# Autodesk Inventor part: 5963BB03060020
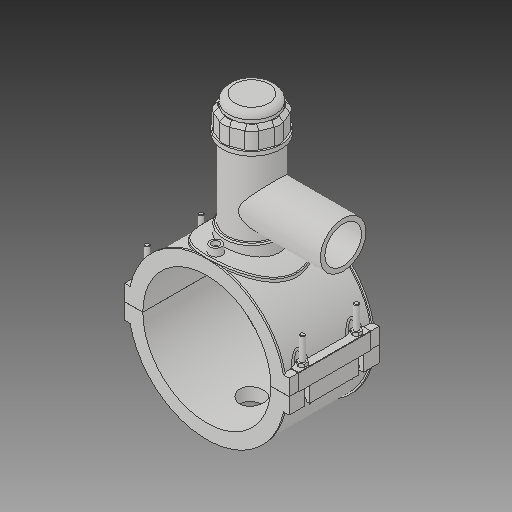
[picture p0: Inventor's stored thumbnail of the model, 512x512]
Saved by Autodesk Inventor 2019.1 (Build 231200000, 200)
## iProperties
Created: 2017-07
Part Number: 5963BB03060020
Material: Generic
Description: PLASSON TAPPING SADDLE 6''IPS x 2''IPS
Document SubType Name: Modeling
Designer: KIM
Mass: 1712.7 g
Surface Area: 2671.49 cm^2
Volume: 1712.7 cm^3
Density: 1 g/cm^3
Appearance: Default
Author: KIM
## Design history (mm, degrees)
derived "5963B.ipt"
feature "Solid1::5963B.ipt"
feature "Solid2::5963B.ipt"
feature "Solid4::5963B.ipt"
feature "Solid5::5963B.ipt"
tag "TaggingFeature1"
body "Solid1"
body "Solid2"
other parameters: "d0" = 168, "d2" = 215.9, "d3" = 42, "d4" = 118.11, "d5" = 0, "d6" = 0.1, "d8" = 0, "d19" = 6, "d20" = 6, "d21" = 70.866, "d23" = 0, "d24" = 35.433, "d26" = 0, "d29" = 3, "d30" = 56, "d31" = 6, "d32" = 0, "d33" = 0, "d34" = 0.6, "d40" = 104.832, "d41" = 117.6, "d43" = 0, "d45" = 0, "d47" = 171.666, "d70" = 15, "d72" = 0, "d73" = 6, "d75" = 5, "d76" = 0, "d77" = 8.4, "d78" = 114, "d79" = 15, "d80" = 47.244, "d82" = 5 deg, "d84" = 4, "d85" = 14, "d86" = 0, "d87" = 3, "d88" = 0, "d89" = 1, "d90" = 1, "d91" = 94.488, "d92" = 0, "d93" = 0.5, "d94" = 88.42105, "d96" = 205.632, "d97" = 2.3622, "d98" = 0, "d102" = 1.68, "d120" = 140 deg, "d121" = 24.228, "d122" = 20 deg, "d123" = 403.2, "d124" = 120.96, "d126" = 0, "d143" = 173.04, "d145" = 25.84615, "d149" = 2.52, "d150" = 28.43077, "d153" = 118.11, "d154" = 0, "d156" = 100.8, "d157" = 160 deg, "d159" = 6.72, "d161" = 2.52, "d162" = 70.866, "d163" = 0, "d164" = 84, "d167" = 16.8, "d168" = 98.34146, "d170" = 3.2805, "d172" = 0, "d173" = 1, "d175" = 84, "d176" = 20 deg, "d177" = 11.76, "d178" = 33.6, "d180" = 0, "d183" = 13.44, "d184" = 9.408, "d185" = 38.38575, "d186" = 38.38575, "d187" = 100.8, "d188" = 10.08, "d189" = 11.76, "d190" = 0, "d191" = 151.2, "d193" = 6.1236, "d194" = 4.13385, "d195" = 90 deg, "d197" = 0, "d199" = 0, "d200" = 16.8, "d202" = 0, "d203" = 177.038, "d204" = 72.618, "d205" = 53.508, "d206" = 64.974, "d207" = 132.7785, "d208" = 138.08964, "d209" = 164.64534, "d210" = 65.7384, "d211" = 76.44, "d212" = 61.152, "d213" = 31.4766, "d216" = 0, "d217" = 16.8, "d218" = 8.4, "d219" = 1.68, "d222" = 168, "d224" = 0, "d230" = 5.04, "d233" = 6, "d236" = 107.95, "d237" = 35.433, "d238" = 6.02433, "d240" = 35.433, "d241" = 35.433, "d242" = 35.433, "d243" = 6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
